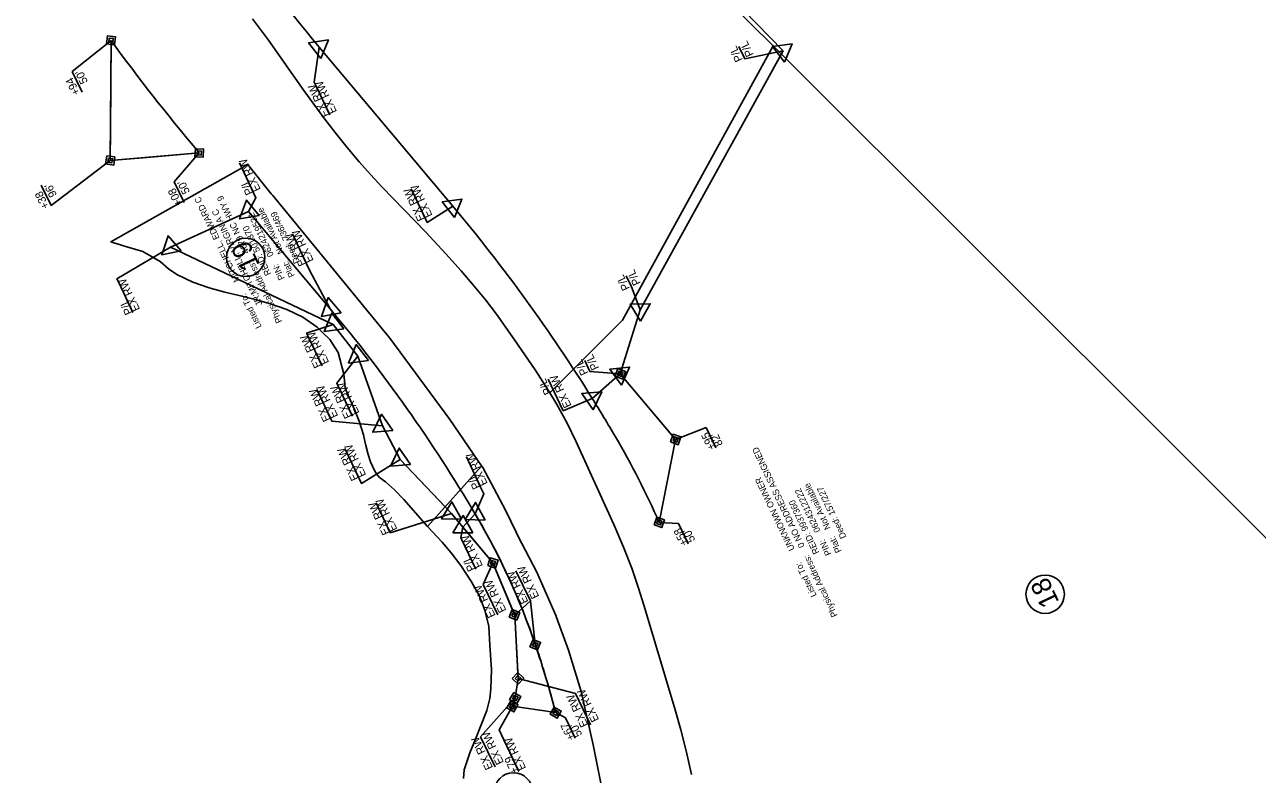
# Model space of a CAD drawing. Extents: x 1019969 to 1024963, y 638146 to 643978.
# Drawn here: x 1022703 to 1023474, y 641093 to 641561 of the extents above; entities that cross this region are included whole.
import ezdxf

# ---------------------------------------------------------------- set-up
doc = ezdxf.new("R2010")
doc.units = 0
for name, color, linetype in [('Old_Level_30', 7, 'Continuous'), ('Pattern 2', 7, 'Continuous'), ('Pattern 3', 7, 'Continuous'), ('Pattern 5', 7, 'Continuous'), ('Prop Easement Permanent Drainage', 7, 'Continuous'), ('Prop Easement Permanent Drainage Station Offsets', 7, 'Continuous'), ('Prop Parcel Number CELL', 7, 'Continuous'), ('Prop Parcel Owner Text', 7, 'Continuous'), ('Prop ROW Marker CELL', 7, 'Continuous'), ('Prop ROW Permanent Easement CELL', 7, 'Continuous'), ('Prop ROW RW Lines', 7, 'Continuous'), ('Prop ROW Station Offsets', 7, 'Continuous'), ('Scratch_Level_4', 7, 'Continuous')]:
    doc.layers.add(name, color=color, linetype=linetype)

msp = doc.modelspace()

# ---------------------------------------------------------------- linework, layer by layer
at = {"layer": 'Old_Level_30'}
for points in [[(1022965.69, 641750.69), (1023171, 641548.25), (1023076.81, 641376.56), (1023031.37, 641331.13), (1023028.87, 641335.19), (1023022.12, 641345.62), (1023009.38, 641364.44), (1022998, 641380.5), (1022991.38, 641389.12), (1022984.13, 641398), (1022975.88, 641407.44), (1022966.31, 641418.19), (1022953.81, 641431.69), (1022926.61, 641459.86), (1022919.31, 641467.75), (1022912.31, 641475.69), (1022904.81, 641484.63), (1022897.12, 641493.99), (1022890.12, 641503.06), (1022877.62, 641520.19), (1022855.62, 641551.62), (1022845.64, 641565.12)], [(1023119.88, 641092.63), (1023116.63, 641107.44), (1023116.42, 641108.25), (1023113.31, 641120.56), (1023109.81, 641132.94), (1023090.37, 641197.94), (1023086.87, 641209.06), (1023082.62, 641221.5), (1023077.37, 641234.75), (1023071.37, 641248.81), (1023047.87, 641300.56), (1023042.12, 641312.25), (1023035.5, 641324.31), (1023031.37, 641331.13), (1023076.81, 641376.56), (1023171, 641548.25), (1023429.39, 641289.91), (1023583.12, 641136.19)], [(1022977.33, 641090.02), (1022977.84, 641095.42), (1022981.41, 641106.09), (1022985.03, 641114.78), (1022991.98, 641132.69), (1022993.83, 641140.15), (1022994.58, 641146.11), (1022994.95, 641158.25), (1022993.82, 641173.56), (1022993.31, 641185.18), (1022990.81, 641195.44), (1022987.13, 641204.5), (1022982.5, 641213), (1022975.81, 641223.25), (1022969.69, 641231.25), (1022964, 641237.87), (1022954.88, 641247.69), (1022988.5, 641285.25), (1022988.78, 641285.55), (1022989.46, 641284.55), (1023003.71, 641257.78), (1023013.75, 641237.25), (1023013.85, 641237.03), (1023023.28, 641219.1), (1023035.27, 641191.67), (1023035.43, 641191.31), (1023043.14, 641170.34), (1023050.91, 641144.45), (1023058.45, 641111.14), (1023061.16, 641097.58), (1023065.12, 641077.76)]]:
    msp.add_lwpolyline(points, dxfattribs=at)
msp.add_lwpolyline([(1022988.5, 641285.25), (1022954.88, 641247.69), (1022940.19, 641264.56), (1022934.31, 641270.63), (1022928.62, 641275.5), (1022925, 641278.19), (1022923.12, 641280.56), (1022921.81, 641282.69), (1022919.31, 641288.13), (1022917.81, 641292.69), (1022916.45, 641298.35), (1022915.8, 641301.03), (1022914.87, 641304.88), (1022912.31, 641313.56), (1022909.37, 641320.81), (1022906.62, 641326.75), (1022903.5, 641334.13), (1022902.87, 641341.06), (1022902.61, 641342.82), (1022899.15, 641356.39), (1022893.91, 641364.55), (1022889.36, 641368.97), (1022885.89, 641372.34), (1022877.01, 641378.54), (1022867.02, 641383.27), (1022856.86, 641386.85), (1022847.13, 641389.56), (1022837.26, 641391.97), (1022828.17, 641394.16), (1022818.43, 641396.84), (1022808.27, 641400.44), (1022798.27, 641405.18), (1022793.06, 641408.79), (1022787.75, 641413.26), (1022776.99, 641419.66), (1022767.11, 641422.46), (1022764.31, 641423.25), (1022763.08, 641423.65), (1022758.81, 641425), (1022757.12, 641425.63), (1022758.53, 641426.42), (1022838.63, 641471.69), (1022842.35, 641474.2), (1022857.28, 641455.57), (1022858.17, 641454.49), (1022915.14, 641385.14), (1022931.39, 641365.34), (1022968.98, 641314.63), (1022986.46, 641288.96), (1022988.78, 641285.55)], close=True, dxfattribs=at)
at = {"layer": 'Pattern 2'}
for p, q in [((1022757.13, 641551.56), (1022756.71, 641495.71)), ((1022779.49, 641478.44), (1022812.3, 641481.19)), ((1022812.3, 641481.19), (1022810.67, 641483.12)), ((1023072.71, 641340.71), (1023062.46, 641331.73)), ((1023075.44, 641343.11), (1023072.71, 641340.71)), ((1023110, 641302.07), (1023075.44, 641343.11)), ((1023075.44, 641343.11), (1023075.44, 641343.11)), ((1023062.46, 641331.73), (1023057.89, 641327.73)), ((1023099.76, 641250.22), (1023110, 641302.07)), ((1023110, 641302.07), (1023110, 641302.07)), ((1022984.75, 641255.47), (1022977.09, 641247.33)), ((1023027.08, 641158.98), (1023026.59, 641160.7))]:
    msp.add_line(p, q, dxfattribs=at)
for points in [[(1022756.71, 641495.71), (1022756.64, 641476.48), (1022779.49, 641478.44)], [(1022977.09, 641247.33), (1022979.03, 641245), (1022995.8, 641224.88), (1023009.32, 641192.46)], [(1023009.32, 641192.46), (1023009.46, 641192.12), (1023011.35, 641155.91), (1023011.52, 641152.7), (1023009.75, 641140.47), (1023007.99, 641135.24), (1023035.06, 641131.3)], [(1023027.12, 641159.01), (1023027.1, 641158.97), (1023027.08, 641158.98)]]:
    msp.add_lwpolyline(points, dxfattribs=at)
for centre, radius, start, end in [((1023780.64, 642297.09), 1266.25, 216.06977, 220.00236), ((1022167.9, 640774.19), 1048.09, 30.35075, 31.88013), ((1022614.53, 641035.71), 530.53, 23.84982, 30.35075), ((1022167.9, 640774.19), 948.09, 30.35075, 30.50587), ((1022614.53, 641035.71), 430.53, 18.65707, 30.35075), ((1022879.58, 641119.82), 152.59, 15.53905, 20.57205), ((1022417.81, 640969.29), 638.16, 15.02954, 17.29513), ((1022417.81, 640969.29), 638.16, 14.86788, 15.02954), ((1022417.81, 640969.29), 638.16, 14.70646, 14.86788)]:
    msp.add_arc(centre, radius, start, end, dxfattribs=at)
at = {"layer": 'Pattern 3'}
for p, q in [((1023177.12, 641545.08), (1022944.22, 641785.22)), ((1022887.28, 641547.4), (1022970.76, 641447.92)), ((1023087.91, 641383.21), (1023177.12, 641545.08)), ((1022843.02, 641444.57), (1022794.23, 641422.33)), ((1022894.16, 641383.64), (1022843.02, 641444.57)), ((1023075.44, 641343.11), (1023087.91, 641383.21)), ((1022977.09, 641247.33), (1022984.75, 641255.47))]:
    msp.add_line(p, q, dxfattribs=at)
for points in [[(1022794.23, 641422.33), (1022896.06, 641373.9), (1022911.32, 641354.22), (1022926.7, 641310.68), (1022937.79, 641289.45), (1022962.41, 641263.76), (1022969.97, 641255.88), (1022977.09, 641247.33)], [(1023057.89, 641327.73), (1023062.46, 641331.73), (1023072.71, 641340.71), (1023075.44, 641343.11)]]:
    msp.add_lwpolyline(points, dxfattribs=at)
for centre, radius, start, end in [((1023780.64, 642297.09), 1166.25, 214.93438, 220.00236), ((1022167.9, 640774.19), 1048.09, 31.88013, 40.00236), ((1022167.9, 640774.19), 948.09, 30.50587, 40.00236)]:
    msp.add_arc(centre, radius, start, end, dxfattribs=at)
at = {"layer": 'Prop Easement Permanent Drainage'}
for p, q in [((1022756.64, 641476.48), (1022757.13, 641551.56)), ((1022812.3, 641481.19), (1022756.64, 641476.48)), ((1023110, 641302.07), (1023075.44, 641343.11)), ((1023099.76, 641250.22), (1023110, 641302.07)), ((1022995.8, 641224.88), (1022977.09, 641247.33)), ((1023009.46, 641192.12), (1022995.8, 641224.88)), ((1023011.52, 641152.7), (1023009.46, 641192.12)), ((1023009.75, 641140.47), (1023011.52, 641152.7)), ((1023007.99, 641135.24), (1023009.75, 641140.47)), ((1023035.06, 641131.3), (1023007.99, 641135.24))]:
    msp.add_line(p, q, dxfattribs=at)
for centre, radius, start, end in [((1022614.53, 641035.71), 430.53, 18.65707, 30.6922), ((1022417.81, 640969.29), 638.16, 14.70646, 18.65707)]:
    msp.add_arc(centre, radius, start, end, dxfattribs=at)
at = {"layer": 'Prop Easement Permanent Drainage Station Offsets'}
for p, q in [((1022732.84, 641532.08), (1022739.04, 641519.13)), ((1022713.54, 641461.11), (1022719.63, 641448.41)), ((1022796.66, 641463.1), (1022802.79, 641450.31)), ((1023129.14, 641309.54), (1023135.14, 641296.89)), ((1023111.87, 641249.63), (1023117.89, 641236.91)), ((1023010.22, 641219.92), (1023019.21, 641201.15)), ((1022989.67, 641211.34), (1022998.78, 641192.34)), ((1023019.21, 641201.15), (1023022.29, 641173.78)), ((1023047.46, 641143.24), (1023056.83, 641123.7)), ((1023041.16, 641128.07), (1023047.24, 641115.24)), ((1022988.15, 641116.24), (1022997.15, 641097.47)), ((1023002.71, 641114.2), (1023012.09, 641094.42))]:
    msp.add_line(p, q, dxfattribs=at)
for points in [[(1022732.84, 641532.08), (1022757.13, 641551.56)], [(1022719.63, 641448.41), (1022756.64, 641476.48)], [(1022796.66, 641463.1), (1022812.3, 641481.19)], [(1023129.14, 641309.54), (1023110, 641302.07)], [(1023111.87, 641249.63), (1023099.76, 641250.22)], [(1022989.67, 641211.34), (1022995.8, 641224.88)], [(1023019.21, 641201.15), (1023009.46, 641192.12)], [(1023047.46, 641143.24), (1023011.52, 641152.7)], [(1022988.15, 641116.24), (1023009.75, 641140.47)], [(1023002.71, 641114.2), (1022999.71, 641120.54), (1023007.99, 641135.24)], [(1023041.16, 641128.07), (1023035.06, 641131.3)]]:
    msp.add_lwpolyline(points, dxfattribs=at)
at = {"layer": 'Prop Parcel Number CELL'}
for p, q in [((1022841.33, 641415.93), (1022841.33, 641415.93)), ((1023340.96, 641205.33), (1023340.96, 641205.33))]:
    msp.add_line(p, q, dxfattribs=at)
for centre in [(1022841.33, 641415.93), (1023340.96, 641205.33), (1023008.62, 641081.72)]:
    msp.add_circle(centre, 12, dxfattribs=at)
at = {"layer": 'Prop ROW Marker CELL'}
for p, q in [((1022757.13, 641551.56), (1022757.13, 641551.56)), ((1022887.28, 641547.4), (1022887.28, 641547.4)), ((1023177.12, 641545.08), (1023177.12, 641545.08)), ((1022756.64, 641476.48), (1022756.64, 641476.48)), ((1022812.3, 641481.19), (1022812.3, 641481.19)), ((1022970.76, 641447.92), (1022970.76, 641447.92)), ((1022843.02, 641444.57), (1022843.02, 641444.57)), ((1022794.23, 641422.33), (1022794.23, 641422.33)), ((1022894.16, 641383.64), (1022894.16, 641383.64)), ((1023087.91, 641383.21), (1023087.91, 641383.21)), ((1022896.06, 641373.9), (1022896.06, 641373.9)), ((1022911.32, 641354.22), (1022911.32, 641354.22)), ((1023075.44, 641343.11), (1023075.44, 641343.11)), ((1023075.44, 641343.11), (1023075.44, 641343.11)), ((1023057.89, 641327.73), (1023057.89, 641327.73)), ((1022926.7, 641310.68), (1022926.7, 641310.68)), ((1023110, 641302.07), (1023110, 641302.07)), ((1022937.79, 641289.45), (1022937.79, 641289.45)), ((1022969.97, 641255.88), (1022969.97, 641255.88)), ((1022984.75, 641255.47), (1022984.75, 641255.47)), ((1022977.09, 641247.33), (1022977.09, 641247.33)), ((1023099.76, 641250.22), (1023099.76, 641250.22)), ((1022995.8, 641224.88), (1022995.8, 641224.88)), ((1023009.32, 641192.46), (1023009.32, 641192.46)), ((1023022.29, 641173.78), (1023022.29, 641173.78)), ((1023011.52, 641152.7), (1023011.52, 641152.7)), ((1023009.75, 641140.47), (1023009.75, 641140.47)), ((1023007.99, 641135.24), (1023007.99, 641135.24)), ((1023035.06, 641131.3), (1023035.06, 641131.3))]:
    msp.add_line(p, q, dxfattribs=at)
for points in [[(1022888.23, 641540.26), (1022880.62, 641550.14), (1022892.98, 641551.82)], [(1023178.08, 641537.93), (1023170.46, 641547.81), (1023182.83, 641549.49)], [(1022849.8, 641442.09), (1022837.5, 641439.95), (1022841.77, 641451.68)], [(1022971.71, 641440.77), (1022964.1, 641450.66), (1022976.46, 641452.34)], [(1022801.06, 641420.02), (1022788.83, 641417.58), (1022792.81, 641429.41)], [(1022900.93, 641381.15), (1022888.63, 641379.02), (1022892.91, 641390.75)], [(1023087.98, 641376), (1023081.64, 641386.74), (1023094.11, 641386.89)], [(1022902.74, 641371.17), (1022890.38, 641369.49), (1022895.08, 641381.05)], [(1022917.97, 641351.43), (1022905.59, 641349.85), (1022910.39, 641361.37)], [(1023076.21, 641335.93), (1023068.85, 641346.01), (1023081.26, 641347.37)], [(1023058.52, 641320.55), (1023051.36, 641330.77), (1023063.79, 641331.88)], [(1022933.2, 641307.57), (1022920.76, 641306.61), (1022926.13, 641317.87)], [(1022944.29, 641286.33), (1022931.85, 641285.37), (1022937.22, 641296.64)], [(1022976.17, 641252.2), (1022963.69, 641252.35), (1022970.04, 641263.09)], [(1022990.89, 641251.67), (1022978.42, 641252.05), (1022984.96, 641262.68)], [(1022983.3, 641243.66), (1022970.83, 641243.78), (1022977.15, 641254.54)]]:
    msp.add_lwpolyline(points, close=True, dxfattribs=at)
at = {"layer": 'Prop ROW Permanent Easement CELL'}
for points in [[(1022754.28, 641549.37), (1022754.94, 641554.42), (1022759.99, 641553.75), (1022759.33, 641548.71)], [(1022755.71, 641550.47), (1022756.04, 641552.99), (1022758.56, 641552.66), (1022758.23, 641550.13)], [(1022809.61, 641478.79), (1022809.89, 641483.87), (1022814.98, 641483.59), (1022814.7, 641478.51)], [(1022754.45, 641479.33), (1022759.49, 641478.67), (1022758.83, 641473.62), (1022753.78, 641474.29)], [(1022755.54, 641477.9), (1022758.07, 641477.57), (1022757.73, 641475.05), (1022755.21, 641475.38)], [(1022810.95, 641479.99), (1022811.09, 641482.53), (1022813.64, 641482.39), (1022813.5, 641479.85)], [(1023072.18, 641341.56), (1023073.9, 641346.36), (1023078.69, 641344.65), (1023076.98, 641339.85)], [(1023073.81, 641342.33), (1023074.67, 641344.73), (1023077.06, 641343.88), (1023076.21, 641341.48)], [(1023106.75, 641300.52), (1023108.46, 641305.32), (1023113.26, 641303.61), (1023111.55, 641298.81)], [(1023108.38, 641301.3), (1023109.23, 641303.69), (1023111.63, 641302.84), (1023110.77, 641300.44)], [(1023096.5, 641248.68), (1023098.22, 641253.48), (1023103.01, 641251.77), (1023101.3, 641246.97)], [(1023098.13, 641249.45), (1023098.99, 641251.85), (1023101.38, 641250.99), (1023100.53, 641248.6)], [(1022992.59, 641223.25), (1022994.17, 641228.09), (1022999.01, 641226.51), (1022997.43, 641221.67)], [(1022994.2, 641224.07), (1022994.99, 641226.49), (1022997.41, 641225.7), (1022996.62, 641223.28)], [(1023006, 641191.06), (1023007.92, 641195.78), (1023012.63, 641193.86), (1023010.72, 641189.14)], [(1023007.66, 641191.76), (1023008.62, 641194.12), (1023010.98, 641193.16), (1023010.02, 641190.8)], [(1023018.98, 641172.38), (1023020.89, 641177.09), (1023025.61, 641175.18), (1023023.69, 641170.46)], [(1023020.64, 641173.08), (1023021.59, 641175.44), (1023023.95, 641174.48), (1023022.99, 641172.12)], [(1023007.92, 641152.61), (1023011.43, 641156.3), (1023015.12, 641152.78), (1023011.6, 641149.1)], [(1023009.72, 641152.66), (1023011.48, 641154.5), (1023013.32, 641152.74), (1023011.56, 641150.9)], [(1023007.07, 641138.72), (1023011.47, 641136.17), (1023008.92, 641131.76), (1023004.51, 641134.32)], [(1023007.53, 641136.98), (1023009.73, 641135.7), (1023008.45, 641133.5), (1023006.25, 641134.78)], [(1023008.82, 641143.95), (1023013.23, 641141.4), (1023010.67, 641137), (1023006.27, 641139.55)], [(1023009.29, 641142.21), (1023011.49, 641140.94), (1023010.21, 641138.73), (1023008.01, 641140.01)], [(1023034.14, 641134.78), (1023038.54, 641132.22), (1023035.99, 641127.82), (1023031.58, 641130.37)], [(1023034.6, 641133.04), (1023036.8, 641131.76), (1023035.53, 641129.56), (1023033.32, 641130.83)]]:
    msp.add_lwpolyline(points, close=True, dxfattribs=at)
at = {"layer": 'Prop ROW RW Lines'}
for p, q in [((1023177.12, 641545.08), (1022944.22, 641785.22)), ((1022970.76, 641447.92), (1022887.28, 641547.4)), ((1023087.91, 641383.21), (1023177.12, 641545.08)), ((1022843.02, 641444.57), (1022794.23, 641422.33)), ((1022894.16, 641383.64), (1022843.02, 641444.57)), ((1023075.44, 641343.11), (1023087.91, 641383.21)), ((1023057.89, 641327.73), (1023075.44, 641343.11)), ((1022977.09, 641247.33), (1022984.75, 641255.47))]:
    msp.add_line(p, q, dxfattribs=at)
msp.add_lwpolyline([(1022977.09, 641247.33), (1022969.97, 641255.88), (1022937.79, 641289.45), (1022926.7, 641310.68), (1022911.32, 641354.22), (1022896.06, 641373.9), (1022794.23, 641422.33)], dxfattribs=at)
for centre, radius, start, end in [((1022167.9, 640774.19), 948.09, 40.00236, 40.00236), ((1023780.64, 642297.09), 1166.25, 214.93438, 220.00236), ((1022167.9, 640774.19), 1048.09, 31.88013, 40.00236), ((1022167.9, 640774.19), 948.09, 30.50587, 40.00236)]:
    msp.add_arc(centre, radius, start, end, dxfattribs=at)
at = {"layer": 'Prop ROW Station Offsets'}
for p, q in [((1023149.56, 641547.78), (1023153.22, 641540.05)), ((1022884.97, 641523.72), (1022893.88, 641504.92)), ((1022837.36, 641475.06), (1022846.26, 641456.26)), ((1022944.72, 641458.79), (1022953.63, 641439.99)), ((1022870.47, 641430.61), (1022879.37, 641411.81)), ((1022761.93, 641400.17), (1022770.83, 641381.37)), ((1023079.13, 641404.46), (1023082.42, 641397.52)), ((1022880.1, 641366.95), (1022889, 641348.15)), ((1023053.16, 641351.48), (1023056.44, 641344.54)), ((1023030.28, 641339.8), (1023039.66, 641319.98)), ((1022885.71, 641333.39), (1022894.62, 641314.59)), ((1022899.08, 641335.36), (1022907.99, 641316.56)), ((1022903.26, 641296.48), (1022912.16, 641277.68)), ((1022979.22, 641291.12), (1022988.12, 641272.32)), ((1022922.75, 641262.54), (1022931.66, 641243.74)), ((1022976.17, 641239.76), (1022985.08, 641220.96))]:
    msp.add_line(p, q, dxfattribs=at)
for points in [[(1022884.97, 641523.72), (1022884.15, 641525.46), (1022887.28, 641547.4)], [(1023153.22, 641540.05), (1023177.12, 641545.08)], [(1022846.26, 641456.26), (1022847.73, 641453.16), (1022843.02, 641444.57)], [(1022953.63, 641439.99), (1022954.7, 641437.72), (1022970.76, 641447.92)], [(1022761.93, 641400.17), (1022760.82, 641402.51), (1022794.23, 641422.33)], [(1022879.37, 641411.81), (1022881.25, 641407.84), (1022894.16, 641383.64)], [(1023082.42, 641397.52), (1023087.91, 641383.21)], [(1022880.1, 641366.95), (1022879.34, 641368.55), (1022896.06, 641373.9)], [(1022899.08, 641335.36), (1022898.22, 641337.19), (1022911.32, 641354.22)], [(1023056.44, 641344.54), (1023075.44, 641343.11)], [(1023039.66, 641319.98), (1023057.89, 641327.73)], [(1022894.62, 641314.59), (1022895.1, 641313.57), (1022926.7, 641310.68)], [(1022912.16, 641277.68), (1022913.63, 641274.58), (1022937.79, 641289.45)], [(1022988.12, 641272.32), (1022990.14, 641268.06), (1022984.75, 641255.47)], [(1022931.66, 641243.74), (1022931.65, 641243.77), (1022969.97, 641255.88)], [(1022976.17, 641239.76), (1022975.69, 641240.78), (1022977.09, 641247.33)]]:
    msp.add_lwpolyline(points, dxfattribs=at)
at = {"layer": 'Scratch_Level_4'}
msp.add_lwpolyline([(1023583.12, 641136.19), (1023429.39, 641289.91), (1023171, 641548.25), (1022965.69, 641750.69), (1022939.88, 641784.81), (1022904.19, 641833.5), (1022797.63, 642006.56), (1022717.5, 641847.75), (1022709.31, 641825.55), (1022708.37, 641828.25), (1022696.87, 641872.69), (1022692.62, 641888.75), (1022682, 641925.56), (1022675.88, 641947.75)], dxfattribs=at)

# ---------------------------------------------------------------- texts
at = {"layer": 'Pattern 5'}
for s, p in [('MITCHELL, EDWARD C ', (1022837.71, 641401.47)), ('4679 NC HWY 9', (1022843.68, 641419.24)), ('JR;MITCHELL, VIRGINIA C', (1022851.92, 641386.64)), ('Not Available', (1022865.34, 641419.04)), ('0624219522', (1022858.97, 641417.32)), ('736/469', (1022868.48, 641427.6)), ('501370', (1022850.48, 641420.06)), ('Deed:', (1022875.33, 641413.14)), ('REID:', (1022857.33, 641405.59)), ('Physical Address:', (1022864.22, 641375.86)), ('PIN:', (1022865.82, 641402.86)), ('Plat:', (1022872.19, 641404.58)), ('Listed To:', (1022851.4, 641372.55)), ('0 NO ADDRESS ASSIGNED', (1023190.8, 641235.46)), ('UNKNOWN OWNER', (1023184.54, 641233.5)), ('0624312222', (1023200.66, 641245.03)), ('Not Available', (1023207.03, 641246.76)), ('157/227', (1023210.02, 641255.64)), ('9937360', (1023193.05, 641245.9)), ('Deed:', (1023216.86, 641241.18)), ('REID:', (1023199.9, 641231.44)), ('PIN:', (1023207.5, 641230.57)), ('Plat:', (1023213.88, 641232.29)), ('Physical Address:', (1023211.35, 641192.08)), ('Listed To:', (1023198.24, 641204.58))]:
    msp.add_text(s, height=4, rotation=115.34303, dxfattribs=at).set_placement(p)
at = {"layer": 'Prop Easement Permanent Drainage Station Offsets'}
for s, rotation, p in [("50'", 115.60299, (1022742.8, 641525.75)), ('+94', 115.60299, (1022737.9, 641518.63)), ("96'", 115.60299, (1022723.45, 641454.89)), ("50'", 115.60299, (1022806.59, 641456.84)), ('+38', 115.60299, (1022718.66, 641447.54)), ('+08', 115.60299, (1022801.8, 641449.48)), ('+95', 115.34303, (1023135.11, 641296.88)), ("82'", 115.34303, (1023139.68, 641299.04)), ('+58', 115.34303, (1023117.87, 641236.9)), ("50'", 115.34303, (1023122.43, 641239.06)), ('EX RW', 115.60299, (1023024.84, 641203.88)), ('EX RW', 115.60299, (1023018.07, 641200.64)), ('EX RW', 115.60299, (1022997.58, 641191.94)), ('EX RW', 115.60299, (1023004.35, 641195.18)), ('EX RW', 115.60299, (1023062.26, 641126.81)), ('EX RW', 115.60299, (1023055.5, 641123.57)), ('+67', 115.34303, (1023047.22, 641115.23)), ("50'", 115.34303, (1023051.78, 641117.39)), ('EX RW', 115.60299, (1022996.01, 641096.95)), ('EX RW', 115.60299, (1023002.77, 641100.19)), ('EX RW', 115.34303, (1023016.63, 641096.57)), ('+79', 115.34303, (1023012.06, 641094.41))]:
    msp.add_text(s, height=5, rotation=rotation, dxfattribs=at).set_placement(p)
at = {"layer": 'Prop Parcel Owner Text'}
for s, p in [('19', (1022850.31, 641411.16)), ('18', (1023349.98, 641200.47))]:
    msp.add_text(s, height=12.15, rotation=115.34303, dxfattribs=at).set_placement(p)
at = {"layer": 'Prop ROW Station Offsets'}
for s, p in [('P/L', (1023152.11, 641539.47)), ('P/L', (1023158.89, 641542.68)), ('EX RW', (1022893.85, 641504.91)), ('EX RW', (1022898.42, 641507.07)), ('EX RW', (1022850.81, 641458.41)), ('P/L', (1022846.24, 641456.25)), ('EX RW', (1022958.17, 641442.14)), ('EX RW', (1022953.6, 641439.98)), ('EX RW', (1022879.35, 641411.8)), ('EX RW', (1022883.91, 641413.96)), ('P/L', (1023088.27, 641399.75)), ('EX RW', (1022775.37, 641383.52)), ('P/L', (1023081.5, 641396.54)), ('P/L', (1022770.81, 641381.36)), ('EX RW', (1022893.55, 641350.3)), ('EX RW', (1022888.98, 641348.14)), ('P/L', (1023062.3, 641346.77)), ('P/L', (1023055.52, 641343.56)), ('EX RW', (1022912.53, 641318.71)), ('P/L', (1023032.86, 641331.42)), ('EX RW', (1023045.06, 641323.18)), ('EX RW', (1022894.6, 641314.58)), ('EX RW', (1022899.16, 641316.74)), ('EX RW', (1022907.96, 641316.55)), ('EX RW', (1022912.14, 641277.67)), ('EX RW', (1022916.7, 641279.83)), ('EX RW', (1022992.66, 641274.47)), ('P/L', (1022988.1, 641272.31)), ('EX RW', (1022931.63, 641243.73)), ('EX RW', (1022936.2, 641245.9)), ('EX RW', (1022989.62, 641223.11)), ('P/L', (1022985.05, 641220.95))]:
    msp.add_text(s, height=5, rotation=115.34303, dxfattribs=at).set_placement(p)

doc.saveas('drawing.dxf')
